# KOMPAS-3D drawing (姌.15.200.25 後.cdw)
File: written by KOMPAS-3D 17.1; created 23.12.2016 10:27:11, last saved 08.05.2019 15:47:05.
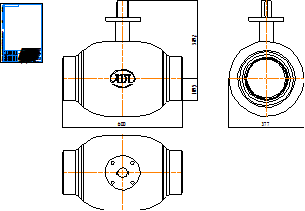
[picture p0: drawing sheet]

Sheet 1: A4, portrait

Title block, sheet 1: name: КШ.15.200.25 сс; material: Внимание! Данный продукт является объектом авторского права ООО «Торговый Дом АДЛ». / Запрещается изменение, копирование, распространение / (в том числе путем копирования на другие сайты и ресурсы в Интернете) / или любое иное использование информации и объектов без предварительного / согласия правообладателя (ООО «Торговый Дом АДЛ»).; sheets: 1; organisation: ООО "Торговый дом АДЛ"; sheet format: A4; stored path: C:\Users\tra\Desktop\2д чертежи\Шаровые краны БИВАЛ\КШ_Бивал_серия_14_15\KOMPAS_2D\КШ.15.200.25 сс.cdw

Views: Вид 1, Проекционный вид 2, Проекционный вид 3
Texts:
  Klimkovich
  ADL
Dimensions and other numbers on the sheet: 600; 389,2; 109,5; 377; 1:1; 1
